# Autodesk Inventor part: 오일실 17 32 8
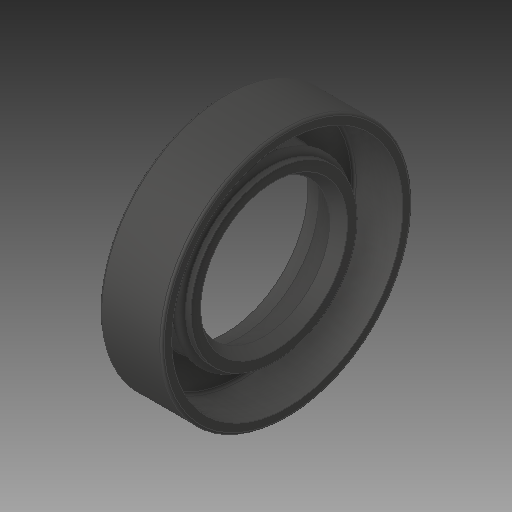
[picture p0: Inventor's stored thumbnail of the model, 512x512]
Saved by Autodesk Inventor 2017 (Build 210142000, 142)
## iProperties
Created: 2024-09
Part Number: 오일실 17 32 8
Material: 일반
Description: 오일-실
Document SubType Name: Modeling
Designer: MRC
Density: 1 g/cm^3
Appearance: 기본값
Author: jhkim
Sending System: Autodesk Inventor 2025
Preprocessor: ST-DEVELOPER v20
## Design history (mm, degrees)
feature "Solid1"
node "솔리드1"
